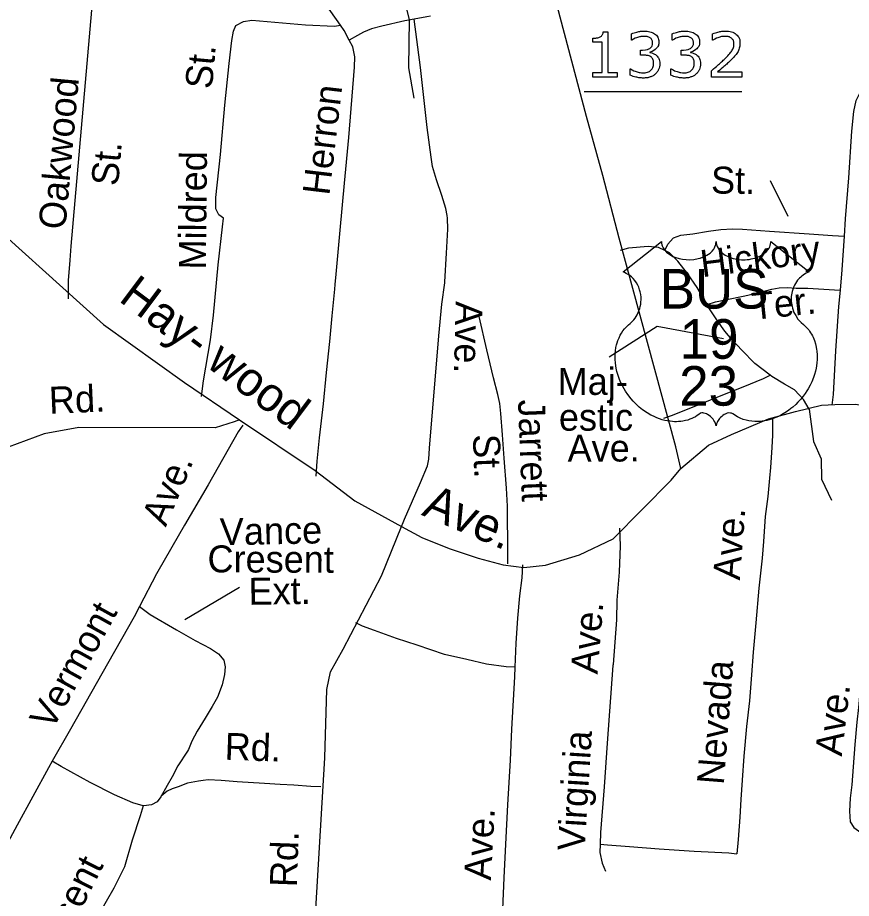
# Model space of a CAD drawing. Extents: x 925297 to 940193, y 663541 to 689899.
# Drawn here: x 928270.8 to 928734.3, y 687878.3 to 688368 of the extents above; entities that cross this region are included whole.
import ezdxf

# ---------------------------------------------------------------- set-up
doc = ezdxf.new("R2010")
doc.units = 0
doc.layers.add('Default', color=7, linetype='Continuous')
doc.layers.add('Old_Level_28', color=7, linetype='Continuous')

msp = doc.modelspace()

# ---------------------------------------------------------------- linework, layer by layer
at = {"layer": 'Default'}
for p, q in [((928585.85, 688326.91), (928673.45, 688326.91)), ((928348.08, 688058.74), (928338.57, 688040.55))]:
    msp.add_line(p, q, dxfattribs=at)
for points in [[(928639.49, 688117.35), (928636.74, 688129.36), (928605.26, 688245.37), (928596.11, 688280.14), (928587.03, 688313.06), (928570.72, 688374.57), (928557.39, 688432.9), (928543.73, 688500.18), (928535.46, 688545.84), (928535.24, 688580.9), (928536.47, 688602.87), (928540.02, 688623.94), (928549.65, 688683.45)], [(928491.23, 688323.13), (928488.24, 688340.05), (928488.77, 688366.85), (928479.65, 688402.41), (928473.74, 688416.23), (928437.3, 688460.76), (928427.13, 688477.94), (928414.15, 688507.23), (928409.89, 688522.18), (928409.41, 688531.01)], [(928450.39, 688363.67), (928441.85, 688375.8), (928431.84, 688390.56), (928413.67, 688416.77), (928400.64, 688437.16), (928391.23, 688451.37), (928387.84, 688456.51), (928383.92, 688459.95), (928381.45, 688461.56)], [(928299.14, 688211.61), (928299.1, 688221.85), (928300.01, 688233.15), (928300.68, 688240.97), (928314.23, 688397.68), (928315.47, 688398.63), (928318.24, 688398.62), (928333.4, 688396.95), (928359.48, 688394.88)], [(928385.22, 688256.5), (928382.78, 688258.25), (928381.11, 688261.65), (928381.03, 688267.92), (928383.64, 688291.89), (928385.97, 688319.28), (928388.39, 688342.52), (928389.99, 688355.19), (928390.93, 688360.4), (928392.09, 688363.58), (928396.43, 688365.79), (928401.08, 688366.44), (928430.84, 688363.92), (928446.99, 688363.12), (928450.39, 688363.67)], [(928491.29, 688367.12), (928486.06, 688366.17), (928473.27, 688363.11), (928467.52, 688361.65), (928463.16, 688359.93), (928459.72, 688357.99), (928455.21, 688355.5)], [(928500.33, 688368.78), (928498.4, 688368.42), (928491.29, 688367.12)], [(928509.56, 688257.99), (928508.9, 688261.87), (928506.61, 688269.05), (928503.74, 688277.82), (928501.53, 688285.11), (928500.74, 688290.34), (928498.55, 688306.88), (928494.86, 688340.3), (928491.29, 688367.12)], [(928455.21, 688355.5), (928452.44, 688360.76), (928450.39, 688363.67)], [(928447.89, 688225.32), (928448.44, 688231.51), (928450.14, 688249.76), (928452.5, 688275.93), (928454.94, 688301.32), (928458.16, 688340.45), (928458.28, 688346.18), (928457.17, 688351.78), (928455.21, 688355.5)], [(928604.05, 688334.91), (928590.52, 688334.91), (928590.52, 688337.46), (928595.73, 688337.46), (928595.73, 688354.22), (928590.52, 688354.22), (928590.52, 688356.5)], [(928596.35, 688359.99), (928598.95, 688359.99), (928598.95, 688337.46), (928604.05, 688337.46), (928604.05, 688334.91)], [(928612.19, 688355.36), (928612.02, 688355.36), (928612.02, 688358.86)], [(928634.84, 688355.36), (928634.67, 688355.36), (928634.67, 688358.86)], [(928657.3, 688355.36), (928657.13, 688355.36), (928657.13, 688358.88)], [(928618.59, 688347.09), (928617.08, 688347.09), (928617.08, 688349.87), (928618.26, 688349.87)], [(928622.32, 688348.82), (928622.32, 688348.58)], [(928641.25, 688347.09), (928639.74, 688347.09), (928639.74, 688349.87), (928640.91, 688349.87)], [(928644.97, 688348.82), (928644.97, 688348.58)], [(928611.3, 688335.96), (928611.3, 688339.46), (928611.56, 688339.46)], [(928633.96, 688335.96), (928633.96, 688339.46), (928634.21, 688339.46)], [(928673.45, 688334.91), (928656.52, 688334.91), (928656.52, 688338.45)], [(928659.99, 688337.81), (928673.45, 688337.81), (928673.45, 688334.91)], [(928730.46, 688246.45), (928731.13, 688256.06), (928732.98, 688278.79), (928734.58, 688304.9), (928735.76, 688315.85), (928737.04, 688321.84), (928738.85, 688325.58)], [(928689.15, 688277.43), (928699.04, 688257.64)], [(928241.11, 688267.08), (928318.6, 688197.33), (928363.64, 688165.14), (928394.2, 688144.38)], [(928508.28, 688221.13), (928509.29, 688237.09), (928509.94, 688250.37), (928509.84, 688256.39), (928509.56, 688257.99)], [(928373.09, 688157.26), (928374.12, 688166.04), (928378.07, 688188.78), (928379.79, 688202.52), (928382.27, 688230.56), (928384.76, 688251.73), (928385.22, 688256.5)], [(928635.32, 688245.38), (928635.52, 688245.61), (928639.43, 688246.97), (928646.28, 688247.74), (928654.84, 688249.28), (928661.74, 688250.17), (928668.27, 688250.47), (928673.85, 688250.31), (928688.87, 688249.32), (928710.84, 688247.67), (928723.78, 688246.75), (928730.46, 688246.45)], [(928630.62, 688238.42), (928632.35, 688242.08), (928635.32, 688245.38)], [(928728.2, 688216.39), (928729.14, 688227.68), (928730.46, 688246.45)], [(928630.62, 688238.42), (928627.14, 688240.2), (928621.34, 688240.79), (928610.44, 688239.72), (928605.83, 688238.4)], [(928654.08, 688208.44), (928648.66, 688217.91), (928643.16, 688225.78), (928637.84, 688232.48), (928633.15, 688237.13), (928630.62, 688238.42)], [(928447.14, 688216.93), (928447.38, 688219.5), (928447.89, 688225.32)], [(928483.43, 688083.2), (928485.94, 688089.08), (928494.72, 688109.43), (928498.62, 688118.8), (928499.41, 688122.51), (928499.74, 688128.66), (928501.02, 688144.44), (928502.98, 688166.44), (928505.02, 688191.01), (928506.73, 688208.65), (928508.24, 688220.56), (928508.28, 688221.13)], [(928436.73, 688113.12), (928437.44, 688121.44), (928438.68, 688134.39), (928440.84, 688153.16), (928442.54, 688170.68), (928444.44, 688187.93), (928445.78, 688202.2), (928447.14, 688216.93)], [(928654.08, 688208.44), (928658.71, 688209.86), (928665.18, 688211.22), (928675.07, 688213.24), (928683.88, 688215.41), (928690.04, 688217), (928694.22, 688217.65), (928698.6, 688218), (928703.7, 688217.62), (928710.18, 688217.54), (928725.01, 688216.61), (928728.2, 688216.39)], [(928723.62, 688152.5), (928724.35, 688158.49), (928725.69, 688182.78), (928727.44, 688207.29), (928728.2, 688216.39)], [(928689.12, 688169.24), (928680.71, 688175.61), (928673.39, 688183.09), (928668.09, 688188.82), (928664.01, 688193.61), (928659.81, 688199.45), (928655.15, 688206.57), (928654.08, 688208.44)], [(928543.33, 688064.29), (928543.44, 688069.83), (928543.24, 688096.42), (928542.58, 688106.37), (928541.24, 688122.98), (928540.34, 688136.05), (928539.52, 688147.86), (928538.89, 688153.36), (928537.77, 688158.49), (928535.3, 688167.71), (928531.7, 688183.24), (928527.4, 688201.81)], [(928599.6, 688179.3), (928626.31, 688196.44), (928663.31, 688189.59)], [(928630.12, 688145.31), (928634.82, 688146.94), (928650.96, 688153.46), (928661.89, 688157.88), (928674.17, 688162.68), (928685.47, 688167.33), (928689.12, 688169.24)], [(928710.85, 688150.36), (928707.63, 688155.65), (928705.3, 688158.31), (928702.66, 688161.1), (928697.14, 688164.16), (928690.09, 688168.5), (928689.12, 688169.24)], [(928710.85, 688150.36), (928713.31, 688132.27), (928717.56, 688122.62), (928717.68, 688111.37), (928723.31, 688099.77)], [(928690.47, 688145.27), (928690.48, 688135.86), (928690.13, 688128.89), (928689.39, 688117.77), (928688.88, 688111.88), (928687.87, 688101.79), (928686.39, 688090.62), (928685.39, 688076.76), (928684.69, 688067.47), (928682.93, 688050.85), (928681.21, 688031.54), (928679.77, 688015.19), (928678.75, 688002.54), (928677.62, 687988.12), (928676.11, 687973.92), (928674.53, 687957.43), (928673.57, 687944.12), (928672.84, 687933.31), (928672.25, 687923.49), (928671.38, 687910.98), (928670.7, 687903.06)], [(928394.2, 688144.38), (928391.21, 688143.27), (928380.73, 688139.89), (928304.96, 688140.07), (928285.61, 688136.51), (928260.43, 688127.23), (928251.75, 688121.42), (928232.87, 688107.83), (928221.24, 688094.85), (928214.67, 688084.72), (928208.86, 688075.89), (928190.39, 688062.03), (928149.94, 688037.39), (928108.98, 688010.05), (928096.93, 687999.03), (928091.62, 687993.77), (928076.58, 687956.12), (928046.58, 687890.75), (928037.88, 687873.87)], [(928396.08, 688141.3), (928393.38, 688137.67), (928376.75, 688108.17), (928363.7, 688085.77), (928348.74, 688060), (928348.08, 688058.74)], [(928394.2, 688144.38), (928436.17, 688116.17), (928458.24, 688099.36), (928484.27, 688085)], [(928484.27, 688085), (928495.45, 688078.87), (928510.65, 688072.91), (928526.88, 688067.39), (928540.7, 688063.67), (928552.32, 688062.33), (928564.36, 688063.52), (928583.27, 688069.33), (928601.86, 688078.12), (928634.14, 688110.87), (928639.49, 688117.35)], [(928422.69, 687400.3), (928414.19, 687437.24), (928414.42, 687448.07), (928414.77, 687474.32), (928419.06, 687574.19), (928422.79, 687634.18), (928425.12, 687675.86), (928427.91, 687706.32), (928429.77, 687756.68), (928430.82, 687763.14), (928433.64, 687822.45), (928441.53, 687956.48), (928442.81, 687994.5), (928444.79, 688004.27), (928451.77, 688016.8), (928473.2, 688057.64), (928484.27, 688085)], [(928605.46, 688084.18), (928605.71, 688074.33), (928605.19, 688059.58), (928604.03, 688044.1), (928603.7, 688033.23), (928601.83, 688008.33), (928601.78, 688007.7), (928598.54, 687964.53), (928596.83, 687940.31), (928594.8, 687914.89), (928594.63, 687908.54)], [(928551.46, 688063.68), (928551.06, 688056.42), (928549.89, 688046.51), (928548.67, 688034.06), (928547.85, 688020.15), (928547.33, 688006.84)], [(928796.19, 688059.95), (928789.8, 688058.52), (928771.6, 688056.34), (928760.59, 688054.51), (928754.37, 688052.94), (928749.47, 688051.22), (928746.42, 688049.25), (928744.53, 688045.37), (928743.33, 688034.1), (928741.47, 688014.91), (928740.15, 688001.75), (928738.99, 687992.68), (928738.31, 687984.52), (928737.4, 687976.21), (928736.32, 687963.78), (928735.28, 687951.46), (928734.6, 687941.41), (928733.67, 687934.06), (928733.22, 687926.81), (928733.69, 687920.8), (928735.67, 687917.63), (928739.63, 687914.86), (928741.01, 687914.47)], [(928394.23, 688051.21), (928363.79, 688033.24)], [(928338.57, 688040.55), (928335.55, 688034.76), (928317.57, 688003.16), (928300.26, 687972.43), (928290.1, 687954.6)], [(928338.57, 688040.55), (928344.48, 688036.15), (928359.19, 688027.59), (928369.62, 688021.69), (928378.08, 688017.19), (928382.53, 688014.28), (928385.47, 688010.83), (928386.2, 688007.09), (928385.79, 688002.86), (928384.5, 687997.04), (928381.98, 687990.15), (928379.03, 687984.98), (928375.18, 687978.48), (928370.74, 687971.35), (928367.73, 687965.73), (928365.85, 687961.01), (928365.3, 687960.17), (928359.94, 687952), (928356.66, 687945.92), (928353.97, 687940.99), (928350.44, 687934.82)], [(928547.33, 688006.84), (928542.51, 688007.09), (928531.54, 688008.54), (928520.51, 688011.06), (928508.19, 688013.92), (928492.91, 688018.99), (928481.45, 688022.81), (928469.3, 688027.24), (928462.5, 688029.73), (928458.84, 688031.45)], [(928547.33, 688006.84), (928547.12, 688001.43), (928545.43, 687972.42), (928544.67, 687955.24), (928543.15, 687930.23), (928542.13, 687908.37), (928541.14, 687889.77), (928540.37, 687872.33), (928539.47, 687845.93), (928539.19, 687840.09)], [(928290.1, 687954.6), (928288, 687950.92), (928270.65, 687919.1), (928258.83, 687897.72), (928255.36, 687891.39)], [(928340.72, 687929.8), (928334.84, 687931.4), (928324.69, 687935.81), (928311.09, 687942.66), (928295.04, 687951.66), (928290.1, 687954.6)], [(928416.82, 687941.71), (928408.1, 687942.18), (928392.96, 687943.13), (928384.05, 687943.89), (928376.73, 687944.24), (928374.04, 687943.85), (928371.45, 687943.47), (928365.27, 687942.35), (928360.01, 687940.37), (928356.69, 687939.21), (928353.93, 687937.98), (928350.63, 687935.07), (928350.44, 687934.82)], [(928439.45, 687940.32), (928433.84, 687940.42), (928424.43, 687941.3), (928416.82, 687941.71)], [(928350.44, 687934.82), (928348.36, 687932.07), (928345.21, 687930.24), (928341.08, 687929.71), (928340.72, 687929.8)], [(928340.72, 687929.8), (928339.01, 687924.22), (928334.57, 687910.76), (928330.26, 687895.79), (928324.28, 687884), (928315.88, 687869.1), (928308.36, 687855.66), (928301.67, 687840.9), (928295.09, 687827.13), (928287.19, 687809.84), (928280.09, 687793.55), (928271.65, 687774.59), (928263.36, 687756.82), (928256.42, 687742.75), (928248.3, 687728.49), (928245.65, 687721.79), (928244.74, 687717.88), (928244.7, 687714.83), (928244.78, 687714.17), (928243.99, 687708.13)], [(928594.63, 687908.54), (928594.5, 687903.82), (928595.82, 687897.85), (928597.55, 687893.39)], [(928594.63, 687908.54), (928598.79, 687908.03), (928610.92, 687907.23), (928627.44, 687905.95), (928646.84, 687904.61), (928666.27, 687903.69), (928670.7, 687903.06)]]:
    msp.add_lwpolyline(points, dxfattribs=at)
msp.add_lwpolyline([(928628.73, 688243.49), (928628.79, 688242.61), (928629, 688241.57), (928629.16, 688241.03), (928629.65, 688240), (928630.46, 688238.78), (928631.58, 688237.59), (928632.85, 688236.55), (928633.7, 688235.99), (928635.15, 688235.22), (928636.8, 688234.52), (928638.63, 688234), (928640.5, 688233.62), (928642.55, 688233.39), (928644.57, 688233.36), (928646.75, 688233.52), (928649.16, 688233.98), (928650.28, 688234.27), (928651.52, 688234.7), (928652.68, 688235.18), (928653.95, 688235.86), (928654.96, 688236.51), (928655.76, 688237.09), (928656.89, 688238.17), (928657.79, 688239.28), (928658.16, 688239.91), (928658.49, 688240.52), (928658.94, 688241.8), (928659.06, 688242.36), (928659.15, 688243.54), (928659.22, 688242.55), (928659.32, 688241.93), (928659.49, 688241.33), (928659.74, 688240.69), (928660.19, 688239.79), (928660.69, 688239.03), (928661.64, 688237.92), (928662.23, 688237.36), (928662.77, 688236.92), (928664.21, 688235.93), (928665.9, 688235.08), (928666.73, 688234.71), (928667.58, 688234.41), (928668.66, 688234.08), (928669.78, 688233.82), (928670.89, 688233.63), (928672.02, 688233.47), (928673.17, 688233.38), (928674.11, 688233.36), (928675.27, 688233.37), (928676.33, 688233.43), (928677.43, 688233.56), (928678.63, 688233.76), (928679.6, 688233.97), (928680.88, 688234.31), (928682.03, 688234.73), (928683.05, 688235.16), (928684.37, 688235.86), (928685.44, 688236.52), (928686.21, 688237.15), (928687.14, 688238), (928688.02, 688239.02), (928688.54, 688239.76), (928688.9, 688240.53), (928689.24, 688241.33), (928689.45, 688242.19), (928689.55, 688242.93), (928689.57, 688243.56), (928710.82, 688226.63), (928710.32, 688226.44), (928709.17, 688225.87), (928708.25, 688225.33), (928706.79, 688224.3), (928706.16, 688223.74), (928705.53, 688223.14), (928704.96, 688222.52), (928704.45, 688221.93), (928703.83, 688221.07), (928703.28, 688220.22), (928702.74, 688219.28), (928702.34, 688218.46), (928701.69, 688216.75), (928701.38, 688215.67), (928701.18, 688214.75), (928700.93, 688212.86), (928700.86, 688211.95), (928700.86, 688211.06), (928700.91, 688210.12), (928701, 688209.22), (928701.16, 688208.27), (928701.32, 688207.45), (928701.58, 688206.43), (928701.96, 688205.25), (928702.42, 688204.1), (928703.39, 688202.26), (928704.64, 688200.37), (928705.53, 688199.32), (928706.41, 688198.41), (928707.72, 688197.31), (928708.43, 688196.68), (928709.25, 688195.86), (928710.58, 688194.32), (928711.12, 688193.59), (928711.67, 688192.78), (928712.17, 688191.93), (928712.67, 688191.03), (928713.07, 688190.24), (928713.82, 688188.42), (928714.36, 688186.65), (928714.62, 688185.72), (928715.01, 688183.63), (928715.16, 688182.6), (928715.32, 688180.57), (928715.33, 688178.11), (928715.14, 688175.77), (928714.7, 688173.04), (928714.34, 688171.41), (928713.78, 688169.51), (928713.24, 688167.87), (928712.27, 688165.45), (928711.41, 688163.69), (928710.29, 688161.63), (928709.53, 688160.38), (928708.63, 688159.05), (928707.52, 688157.52), (928706.21, 688155.89), (928704.64, 688154.17), (928703.37, 688152.9), (928701.72, 688151.42), (928700.71, 688150.59), (928699.28, 688149.51), (928697.32, 688148.2), (928695.39, 688147.08), (928693.75, 688146.24), (928692.29, 688145.61), (928690.41, 688144.9), (928687.27, 688144.03), (928686.13, 688143.79), (928684.77, 688143.59), (928683.5, 688143.47), (928682.27, 688143.39), (928680.62, 688143.39), (928678.97, 688143.52), (928677.41, 688143.74), (928675.79, 688144.08), (928674.1, 688144.58), (928672.56, 688145.19), (928671.01, 688145.95), (928668.38, 688147.61), (928667.62, 688148.01), (928667.19, 688148.13), (928666.17, 688148.18), (928665.22, 688147.97), (928664.24, 688147.58), (928663.65, 688147.27), (928662.86, 688146.76), (928662.26, 688146.28), (928661.53, 688145.59), (928661.03, 688145.01), (928660.65, 688144.56), (928659.91, 688143.39), (928659.64, 688142.84), (928659.37, 688142.12), (928659.13, 688141.07), (928658.79, 688142.4), (928658.4, 688143.28), (928657.95, 688144.03), (928657.48, 688144.7), (928656.74, 688145.55), (928656.07, 688146.19), (928655.27, 688146.84), (928654.42, 688147.36), (928653.73, 688147.71), (928653.1, 688147.95), (928652.34, 688148.14), (928651.71, 688148.19), (928651.2, 688148.18), (928650.49, 688148.01), (928649.53, 688147.32), (928648.62, 688146.69), (928647.63, 688146.08), (928646.44, 688145.45), (928645.58, 688145.05), (928644.55, 688144.65), (928643.34, 688144.24), (928642.04, 688143.9), (928640.7, 688143.64), (928639.52, 688143.45), (928638.25, 688143.34), (928637.11, 688143.3), (928635.91, 688143.31), (928634.8, 688143.4), (928633.5, 688143.52), (928631.9, 688143.75), (928630.57, 688144.06), (928629.16, 688144.43), (928627.72, 688144.88), (928626.17, 688145.48), (928624.24, 688146.32), (928622.9, 688147.01), (928620.77, 688148.23), (928618.29, 688149.95), (928616.41, 688151.47), (928615.04, 688152.71), (928613.02, 688154.77), (928611.83, 688156.11), (928609.97, 688158.52), (928608.77, 688160.27), (928608, 688161.55), (928606.87, 688163.61), (928606.25, 688164.9), (928605.45, 688166.79), (928604.81, 688168.51), (928604.29, 688170.14), (928604, 688171.18), (928603.6, 688173.01), (928603.36, 688174.3), (928603.12, 688176.07), (928602.99, 688177.94), (928602.96, 688179.66), (928603.01, 688181.09), (928603.17, 688182.76), (928603.45, 688184.54), (928603.79, 688186.06), (928604.1, 688187.15), (928604.55, 688188.48), (928605.15, 688189.95), (928605.85, 688191.36), (928606.52, 688192.52), (928607.36, 688193.78), (928608.19, 688194.85), (928609.28, 688196.03), (928610.41, 688197.11), (928611.44, 688197.95), (928612.67, 688199.16), (928613.31, 688199.88), (928614.08, 688200.9), (928614.7, 688201.84), (928615.19, 688202.68), (928615.84, 688203.93), (928616.22, 688204.86), (928616.71, 688206.29), (928616.96, 688207.29), (928617.21, 688208.59), (928617.37, 688209.81), (928617.44, 688211.33), (928617.4, 688212.58), (928617.23, 688214.05), (928616.96, 688215.46), (928616.63, 688216.69), (928616.1, 688218.1), (928615.62, 688219.13), (928614.8, 688220.52), (928613.9, 688221.81), (928612.96, 688222.87), (928612.02, 688223.81), (928611.12, 688224.51), (928610.26, 688225.13), (928609.18, 688225.78), (928608.13, 688226.3), (928607.48, 688226.56)], close=True, dxfattribs=at)
for points in [[(928612.02, 688358.86), (928613.21, 688359.45), (928615.2, 688359.95), (928617.19, 688360.44), (928619.06, 688360.44), (928620.89, 688360.44), (928622.29, 688360.1), (928623.68, 688359.77), (928624.81, 688359.03), (928626.02, 688358.22), (928626.64, 688357.08), (928627.26, 688355.94), (928627.26, 688354.41), (928627.26, 688352.33), (928625.79, 688350.77), (928624.32, 688349.22), (928622.32, 688348.82)], [(928634.67, 688358.86), (928635.87, 688359.45), (928637.86, 688359.95), (928639.85, 688360.44), (928641.72, 688360.44), (928643.55, 688360.44), (928644.94, 688360.1), (928646.34, 688359.77), (928647.47, 688359.03), (928648.68, 688358.22), (928649.3, 688357.08), (928649.92, 688355.94), (928649.92, 688354.41), (928649.92, 688352.33), (928648.45, 688350.77), (928646.98, 688349.22), (928644.97, 688348.82)], [(928657.13, 688358.88), (928658.32, 688359.47), (928660.31, 688359.95), (928662.31, 688360.44), (928664.17, 688360.44), (928668.02, 688360.44), (928670.21, 688358.59), (928672.39, 688356.73), (928672.39, 688353.56), (928672.39, 688352.14), (928672.03, 688350.9), (928671.67, 688349.67), (928670.96, 688348.56), (928670.31, 688347.52), (928669.43, 688346.52), (928668.55, 688345.51), (928667.29, 688344.28), (928665.49, 688342.52), (928663.57, 688340.87), (928661.66, 688339.22), (928659.99, 688337.81)], [(928590.52, 688356.5), (928591.58, 688356.5), (928592.79, 688356.68), (928594, 688356.85), (928594.62, 688357.19), (928595.39, 688357.61), (928595.84, 688358.26), (928596.28, 688358.9), (928596.35, 688359.99)], [(928618.26, 688349.87), (928620.81, 688349.87), (928622.33, 688350.94), (928623.85, 688352.01), (928623.85, 688354.06), (928623.85, 688354.97), (928623.47, 688355.65), (928623.08, 688356.33), (928622.39, 688356.77), (928621.67, 688357.21), (928620.84, 688357.37), (928620.02, 688357.54), (928618.98, 688357.54), (928617.38, 688357.54), (928615.58, 688356.97), (928613.78, 688356.4), (928612.19, 688355.36)], [(928640.91, 688349.87), (928643.47, 688349.87), (928644.99, 688350.94), (928646.51, 688352.01), (928646.51, 688354.06), (928646.51, 688354.97), (928646.12, 688355.65), (928645.74, 688356.33), (928645.05, 688356.77), (928644.33, 688357.21), (928643.5, 688357.37), (928642.68, 688357.54), (928641.64, 688357.54), (928640.04, 688357.54), (928638.24, 688356.97), (928636.44, 688356.4), (928634.84, 688355.36)], [(928656.52, 688338.45), (928658.28, 688339.96), (928660.06, 688341.47), (928661.83, 688342.98), (928663.36, 688344.47), (928666.6, 688347.59), (928667.79, 688349.43), (928668.98, 688351.27), (928668.98, 688353.4), (928668.98, 688355.34), (928667.7, 688356.44), (928666.41, 688357.54), (928664.1, 688357.54), (928662.57, 688357.54), (928660.78, 688357.01), (928659, 688356.47), (928657.3, 688355.36)], [(928625.93, 688346.95), (928626.73, 688346.23), (928627.25, 688345.14), (928627.77, 688344.04), (928627.77, 688342.31), (928627.77, 688340.6), (928627.15, 688339.17), (928626.53, 688337.74), (928625.41, 688336.68), (928624.15, 688335.51), (928622.44, 688334.94), (928620.74, 688334.38), (928618.71, 688334.38), (928616.63, 688334.38), (928614.61, 688334.87), (928612.6, 688335.37), (928611.3, 688335.96)], [(928611.56, 688339.46), (928612.98, 688338.52), (928614.92, 688337.9), (928616.85, 688337.28), (928618.65, 688337.28), (928619.71, 688337.28), (928620.9, 688337.63), (928622.09, 688337.98), (928622.83, 688338.67), (928623.61, 688339.42), (928623.99, 688340.31), (928624.36, 688341.2), (928624.36, 688342.56), (928624.36, 688343.91), (928623.94, 688344.8), (928623.51, 688345.68), (928622.75, 688346.18), (928621.99, 688346.71), (928620.92, 688346.9), (928619.84, 688347.09), (928618.59, 688347.09)], [(928622.32, 688348.58), (928623.12, 688348.45), (928624.16, 688348.02), (928625.2, 688347.59), (928625.93, 688346.95)], [(928648.58, 688346.95), (928649.39, 688346.23), (928649.91, 688345.14), (928650.43, 688344.04), (928650.43, 688342.31), (928650.43, 688340.6), (928649.81, 688339.17), (928649.19, 688337.74), (928648.06, 688336.68), (928646.8, 688335.51), (928645.1, 688334.94), (928643.4, 688334.38), (928641.36, 688334.38), (928639.28, 688334.38), (928637.27, 688334.87), (928635.25, 688335.37), (928633.96, 688335.96)], [(928634.21, 688339.46), (928635.64, 688338.52), (928637.57, 688337.9), (928639.51, 688337.28), (928641.31, 688337.28), (928642.37, 688337.28), (928643.56, 688337.63), (928644.75, 688337.98), (928645.49, 688338.67), (928646.27, 688339.42), (928646.64, 688340.31), (928647.02, 688341.2), (928647.02, 688342.56), (928647.02, 688343.91), (928646.59, 688344.8), (928646.16, 688345.68), (928645.41, 688346.18), (928644.65, 688346.71), (928643.57, 688346.9), (928642.5, 688347.09), (928641.25, 688347.09)], [(928644.97, 688348.58), (928645.78, 688348.45), (928646.82, 688348.02), (928647.86, 688347.59), (928648.58, 688346.95)]]:
    msp.add_open_spline(points, degree=3, dxfattribs=at)
at = {"layer": 'Old_Level_28'}
for points in [[(928241.11, 688267.08), (928318.6, 688197.33), (928363.64, 688165.14), (928394.2, 688144.38)], [(928639.49, 688117.35), (928654.87, 688130.19), (928667.72, 688136.23), (928688.3, 688144.9), (928703.27, 688148.91), (928717.66, 688152.47), (928725.18, 688152.94), (928736.48, 688153.09), (928770.68, 688148.21), (928827.03, 688133.76), (928849.33, 688129.77), (928872.49, 688128.91), (928908.64, 688131.6), (928919.8, 688131.64), (928939.04, 688132.57), (928957.06, 688131.75), (928972.56, 688128.16), (928997.1, 688121.24), (929012.71, 688116.14), (929028.65, 688108.55), (929037.28, 688102.7), (929050.12, 688094.96), (929057.7, 688090.16), (929073.52, 688081.89)], [(928394.2, 688144.38), (928436.17, 688116.17), (928458.24, 688099.36), (928484.27, 688085)], [(928484.27, 688085), (928495.45, 688078.87), (928510.65, 688072.91), (928526.88, 688067.39), (928540.7, 688063.67), (928552.32, 688062.33), (928564.36, 688063.52), (928583.27, 688069.33), (928601.86, 688078.12), (928634.14, 688110.87), (928639.49, 688117.35)]]:
    msp.add_lwpolyline(points, dxfattribs=at)

# ---------------------------------------------------------------- texts
at = {"layer": 'Default'}
for s, height, rotation, p in [('St.', 15, 84.8003, (928378.85, 688327.92)), ('Oakwood', 15, 84.8672, (928297.36, 688249.79)), ('Herron', 15, 83.2379, (928444.1, 688268.76)), ('St.', 15, 84.8672, (928326.65, 688274.03)), ('Mildred', 15, 89.4466, (928375.5, 688227.86)), ('St.', 15, 359.3209, (928656.24, 688270.17)), ('Hickory', 15, 7.2434, (928651.37, 688223.62)), ('Hay- wood', 19, 323.1583, (928326.43, 688210.74)), ('Ter.', 15, 5.9254, (928679.81, 688199.9)), ('Ave.', 15, 268.7141, (928514.32, 688210.4)), ('Maj-', 15, 0.1028, (928571.05, 688158.17)), ('Rd.', 15, 2.4441, (928288.56, 688147.67)), ('Jarrett', 15, 272.2609, (928548.97, 688155.45)), ('estic', 15, 0.1028, (928571.75, 688138.29)), ('St.', 15, 272.1766, (928523.89, 688136.19)), ('Ave.', 15, 0.2497, (928576.57, 688121.04)), ('Ave.', 15, 67.1542, (928353.21, 688084.45)), ('Ave.', 19, 337.0024, (928494.87, 688091.58)), ('Ave.', 15, 85.5118, (928672.3, 688054.95)), ('Vance', 15, 1.1471, (928383.39, 688074.56)), ('Cresent', 15, 359.7503, (928376.38, 688059.57)), ('Ext.', 15, 0.8996, (928399.31, 688041.47)), ('Vermont', 15, 61.036, (928289.96, 687971.23)), ('Ave.', 15, 85.2731, (928593.21, 688002.7)), ('Nevada', 15, 85.5118, (928663.37, 687941.18)), ('Ave.', 15, 83.2572, (928728.98, 687956.98)), ('Rd.', 15, 358.0076, (928385.76, 687955.42)), ('Virginia', 15, 86.4369, (928585.98, 687904.37)), ('Ave.', 15, 86.8829, (928533.96, 687888.12)), ('Rd.', 15, 87.9579, (928426, 687884.38)), ('Cresent', 15, 63.1999, (928287.19, 687834.17))]:
    msp.add_text(s, height=height, rotation=rotation, dxfattribs=at).set_placement(p)
for s, p in [('BUS', (928627.76, 688206.18)), ('19', (928638.85, 688178.32)), ('23', (928638.62, 688152.23))]:
    msp.add_text(s, height=22, dxfattribs=at).set_placement(p)

doc.saveas('drawing.dxf')
